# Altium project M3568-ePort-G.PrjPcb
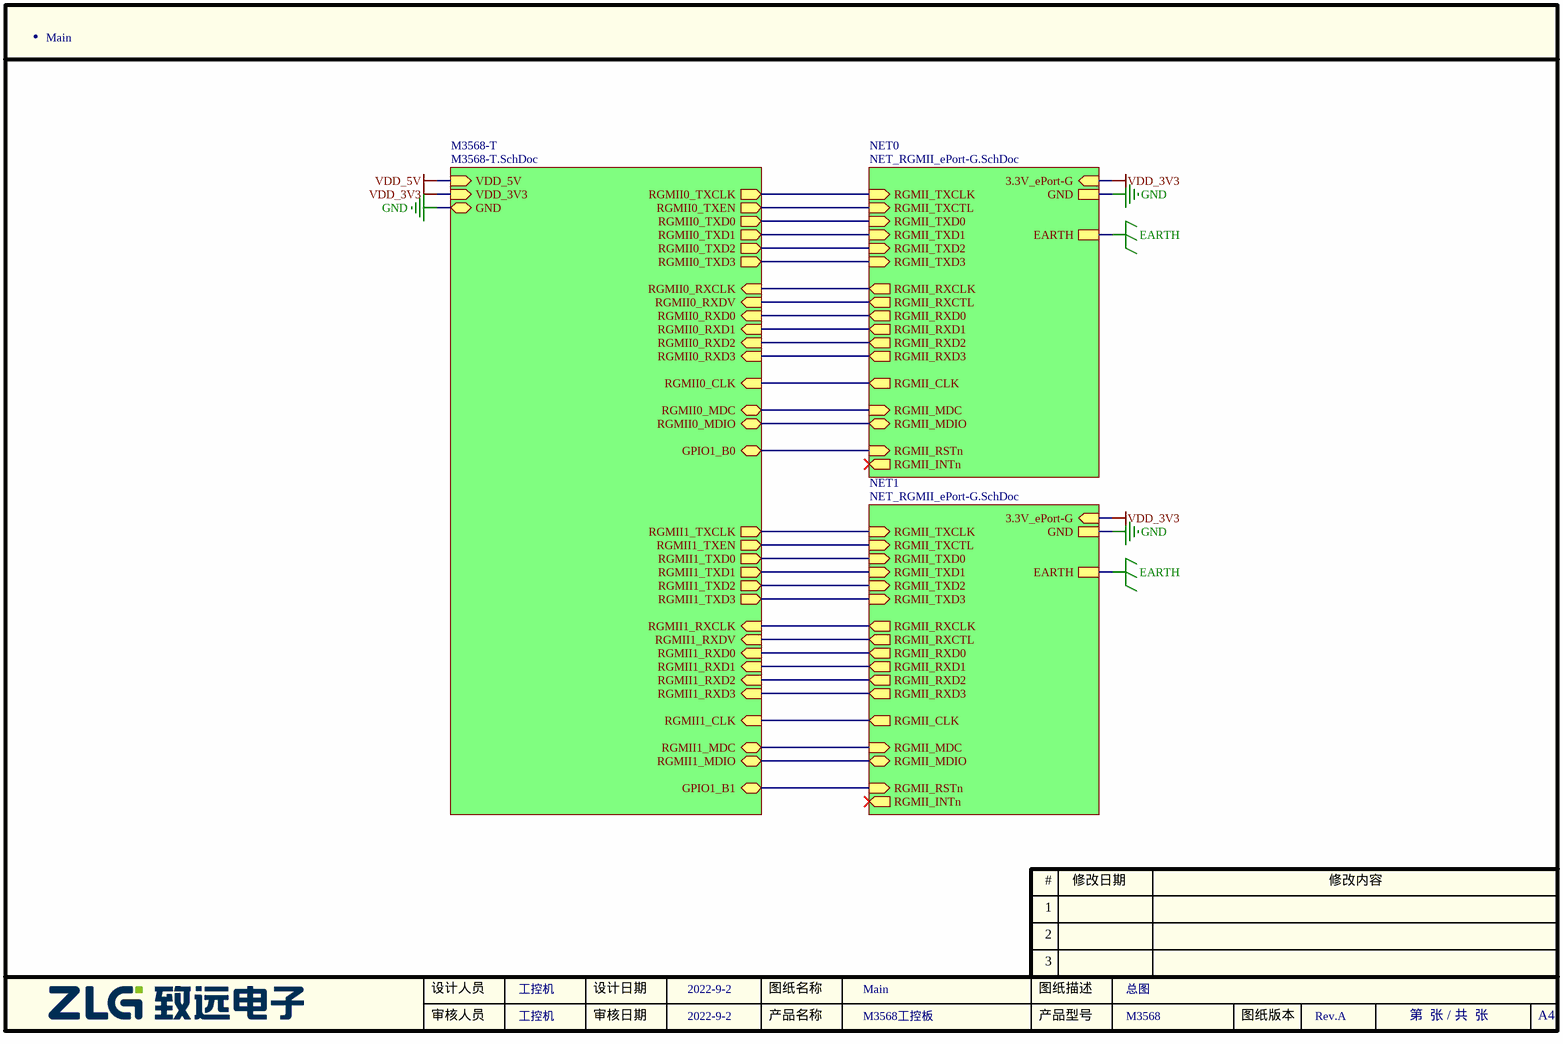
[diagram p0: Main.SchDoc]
3 sheets, 72 parts. Net scope: hierarchical (ports join the sheet entries above them; power ports are global).
Sheets:
  Main.SchDoc
    M3568-T = M3568-T.SchDoc
    NET0 = NET_RGMII_ePort-G.SchDoc
    NET1 = NET_RGMII_ePort-G.SchDoc

## Sheet Main.SchDoc
size A4; PageSetup: Record=PageOptions¦CenterHorizontal=True¦CenterVertical=True¦PrintScale=1.00¦XCorrection=1.00¦YCorrection=1.00¦PrintKind=0¦BorderSize=5000000¦LeftOffset=0¦BottomOffset=0¦Orientation=2¦PaperLength=1000¦PaperWidth=1000¦Scale=100¦PaperSource=7¦PrintQuality=600¦MediaType=1¦DitherType=10¦PaperKind=A4¦PrintScaleMode=1

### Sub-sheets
M3568-T = M3568-T.SchDoc: VDD_5V (in), VDD_3V3 (in), GND (bidir), RGMII1_TXEN (out), RGMII1_TXCLK (out), RGMII1_TXD3 (out), RGMII1_TXD2 (out), RGMII1_TXD1 (out), RGMII1_TXD0 (out), RGMII1_MDC (bidir), RGMII1_MDIO (bidir), RGMII1_CLK (in), RGMII1_RXD2 (in), RGMII1_RXD3 (in), RGMII1_RXD0 (in), RGMII1_RXD1 (in), RGMII1_RXCLK (in), RGMII1_RXDV (in), RGMII0_TXD3 (out), RGMII0_TXD2 (out), RGMII0_TXD1 (out), RGMII0_TXD0 (out), RGMII0_TXEN (out), RGMII0_TXCLK (out), RGMII0_MDIO (bidir), RGMII0_RXD3 (in), RGMII0_RXD2 (in), RGMII0_RXD1 (in), RGMII0_RXD0 (in), RGMII0_RXDV (in), RGMII0_RXCLK (in), RGMII0_MDC (bidir), RGMII0_CLK (in), GPIO1_B1 (bidir), GPIO1_B0 (bidir)
NET0 = NET_RGMII_ePort-G.SchDoc: GND, RGMII_INTn (out), RGMII_RXD0 (out), RGMII_RXD2 (out), RGMII_RXCTL (out), RGMII_RXD1 (out), RGMII_TXCLK (in), RGMII_RXD3 (out), RGMII_TXD2 (in), RGMII_MDIO (bidir), RGMII_TXD3 (in), RGMII_TXCTL (in), RGMII_TXD1 (in), RGMII_RXCLK (out), RGMII_MDC (in), RGMII_TXD0 (in), RGMII_RSTn (in), EARTH, RGMII_CLK (out), 3.3V_ePort-G (in)
NET1 = NET_RGMII_ePort-G.SchDoc: GND, RGMII_INTn (out), RGMII_RXD0 (out), RGMII_RXD2 (out), RGMII_RXCTL (out), RGMII_RXD1 (out), RGMII_TXCLK (in), RGMII_RXD3 (out), RGMII_TXD2 (in), RGMII_MDIO (bidir), RGMII_TXD3 (in), RGMII_TXCTL (in), RGMII_TXD1 (in), RGMII_RXCLK (out), RGMII_MDC (in), RGMII_TXD0 (in), RGMII_RSTn (in), EARTH, RGMII_CLK (out), 3.3V_ePort-G (in)

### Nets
EARTH: sheet NET0/EARTH, sheet NET1/EARTH
GND: sheet M3568-T/GND, sheet NET0/GND, sheet NET1/GND
VDD_3V3: sheet M3568-T/VDD_3V3, sheet NET0/3.3V_ePort-G, sheet NET1/3.3V_ePort-G  [project net 3.3V_ePort-G]
RGMII_CLK: sheet M3568-T/RGMII1_CLK, sheet NET1/RGMII_CLK
RGMII_CLK: sheet M3568-T/RGMII0_CLK, sheet NET0/RGMII_CLK  [a separate net that carries the same name]
RGMII_MDC: sheet M3568-T/RGMII1_MDC, sheet NET1/RGMII_MDC
RGMII_MDC: sheet M3568-T/RGMII0_MDC, sheet NET0/RGMII_MDC  [a separate net that carries the same name]
RGMII_MDIO: sheet M3568-T/RGMII1_MDIO, sheet NET1/RGMII_MDIO
RGMII_MDIO: sheet M3568-T/RGMII0_MDIO, sheet NET0/RGMII_MDIO  [a separate net that carries the same name]
RGMII_RSTn: sheet M3568-T/GPIO1_B1, sheet NET1/RGMII_RSTn
RGMII_RSTn: sheet M3568-T/GPIO1_B0, sheet NET0/RGMII_RSTn  [a separate net that carries the same name]
RGMII_RXCLK: sheet M3568-T/RGMII1_RXCLK, sheet NET1/RGMII_RXCLK
RGMII_RXCLK: sheet M3568-T/RGMII0_RXCLK, sheet NET0/RGMII_RXCLK  [a separate net that carries the same name]
RGMII_RXCTL: sheet M3568-T/RGMII1_RXDV, sheet NET1/RGMII_RXCTL
RGMII_RXCTL: sheet M3568-T/RGMII0_RXDV, sheet NET0/RGMII_RXCTL  [a separate net that carries the same name]
RGMII_RXD0: sheet M3568-T/RGMII1_RXD0, sheet NET1/RGMII_RXD0
RGMII_RXD0: sheet M3568-T/RGMII0_RXD0, sheet NET0/RGMII_RXD0  [a separate net that carries the same name]
RGMII_RXD1: sheet M3568-T/RGMII1_RXD1, sheet NET1/RGMII_RXD1
RGMII_RXD1: sheet M3568-T/RGMII0_RXD1, sheet NET0/RGMII_RXD1  [a separate net that carries the same name]
RGMII_RXD2: sheet M3568-T/RGMII1_RXD2, sheet NET1/RGMII_RXD2
RGMII_RXD2: sheet M3568-T/RGMII0_RXD2, sheet NET0/RGMII_RXD2  [a separate net that carries the same name]
RGMII_RXD3: sheet M3568-T/RGMII1_RXD3, sheet NET1/RGMII_RXD3
RGMII_RXD3: sheet M3568-T/RGMII0_RXD3, sheet NET0/RGMII_RXD3  [a separate net that carries the same name]
RGMII_TXCLK: sheet M3568-T/RGMII1_TXCLK, sheet NET1/RGMII_TXCLK
RGMII_TXCLK: sheet M3568-T/RGMII0_TXCLK, sheet NET0/RGMII_TXCLK  [a separate net that carries the same name]
RGMII_TXCTL: sheet M3568-T/RGMII1_TXEN, sheet NET1/RGMII_TXCTL
RGMII_TXCTL: sheet M3568-T/RGMII0_TXEN, sheet NET0/RGMII_TXCTL  [a separate net that carries the same name]
RGMII_TXD0: sheet M3568-T/RGMII1_TXD0, sheet NET1/RGMII_TXD0
RGMII_TXD0: sheet M3568-T/RGMII0_TXD0, sheet NET0/RGMII_TXD0  [a separate net that carries the same name]
RGMII_TXD1: sheet M3568-T/RGMII1_TXD1, sheet NET1/RGMII_TXD1
RGMII_TXD1: sheet M3568-T/RGMII0_TXD1, sheet NET0/RGMII_TXD1  [a separate net that carries the same name]
RGMII_TXD2: sheet M3568-T/RGMII1_TXD2, sheet NET1/RGMII_TXD2
RGMII_TXD2: sheet M3568-T/RGMII0_TXD2, sheet NET0/RGMII_TXD2  [a separate net that carries the same name]
RGMII_TXD3: sheet M3568-T/RGMII1_TXD3, sheet NET1/RGMII_TXD3
RGMII_TXD3: sheet M3568-T/RGMII0_TXD3, sheet NET0/RGMII_TXD3  [a separate net that carries the same name]

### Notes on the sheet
- Main
- 工控机
- 2022-9-2
- M3568工控板
- 总图
- M3568
- Rev.A

## Sheet M3568-T.SchDoc
size A3; PageSetup: Record=PageOptions¦CenterHorizontal=True¦CenterVertical=True¦PrintScale=1.00¦XCorrection=1.00¦YCorrection=1.00¦PrintKind=0¦BorderSize=5000000¦LeftOffset=0¦BottomOffset=0¦Orientation=2¦PaperLength=1000¦PaperWidth=1000¦Scale=100¦PaperSource=7¦PrintQuality=600¦MediaType=1¦DitherType=10¦PaperKind=A4¦PrintScaleMode=1
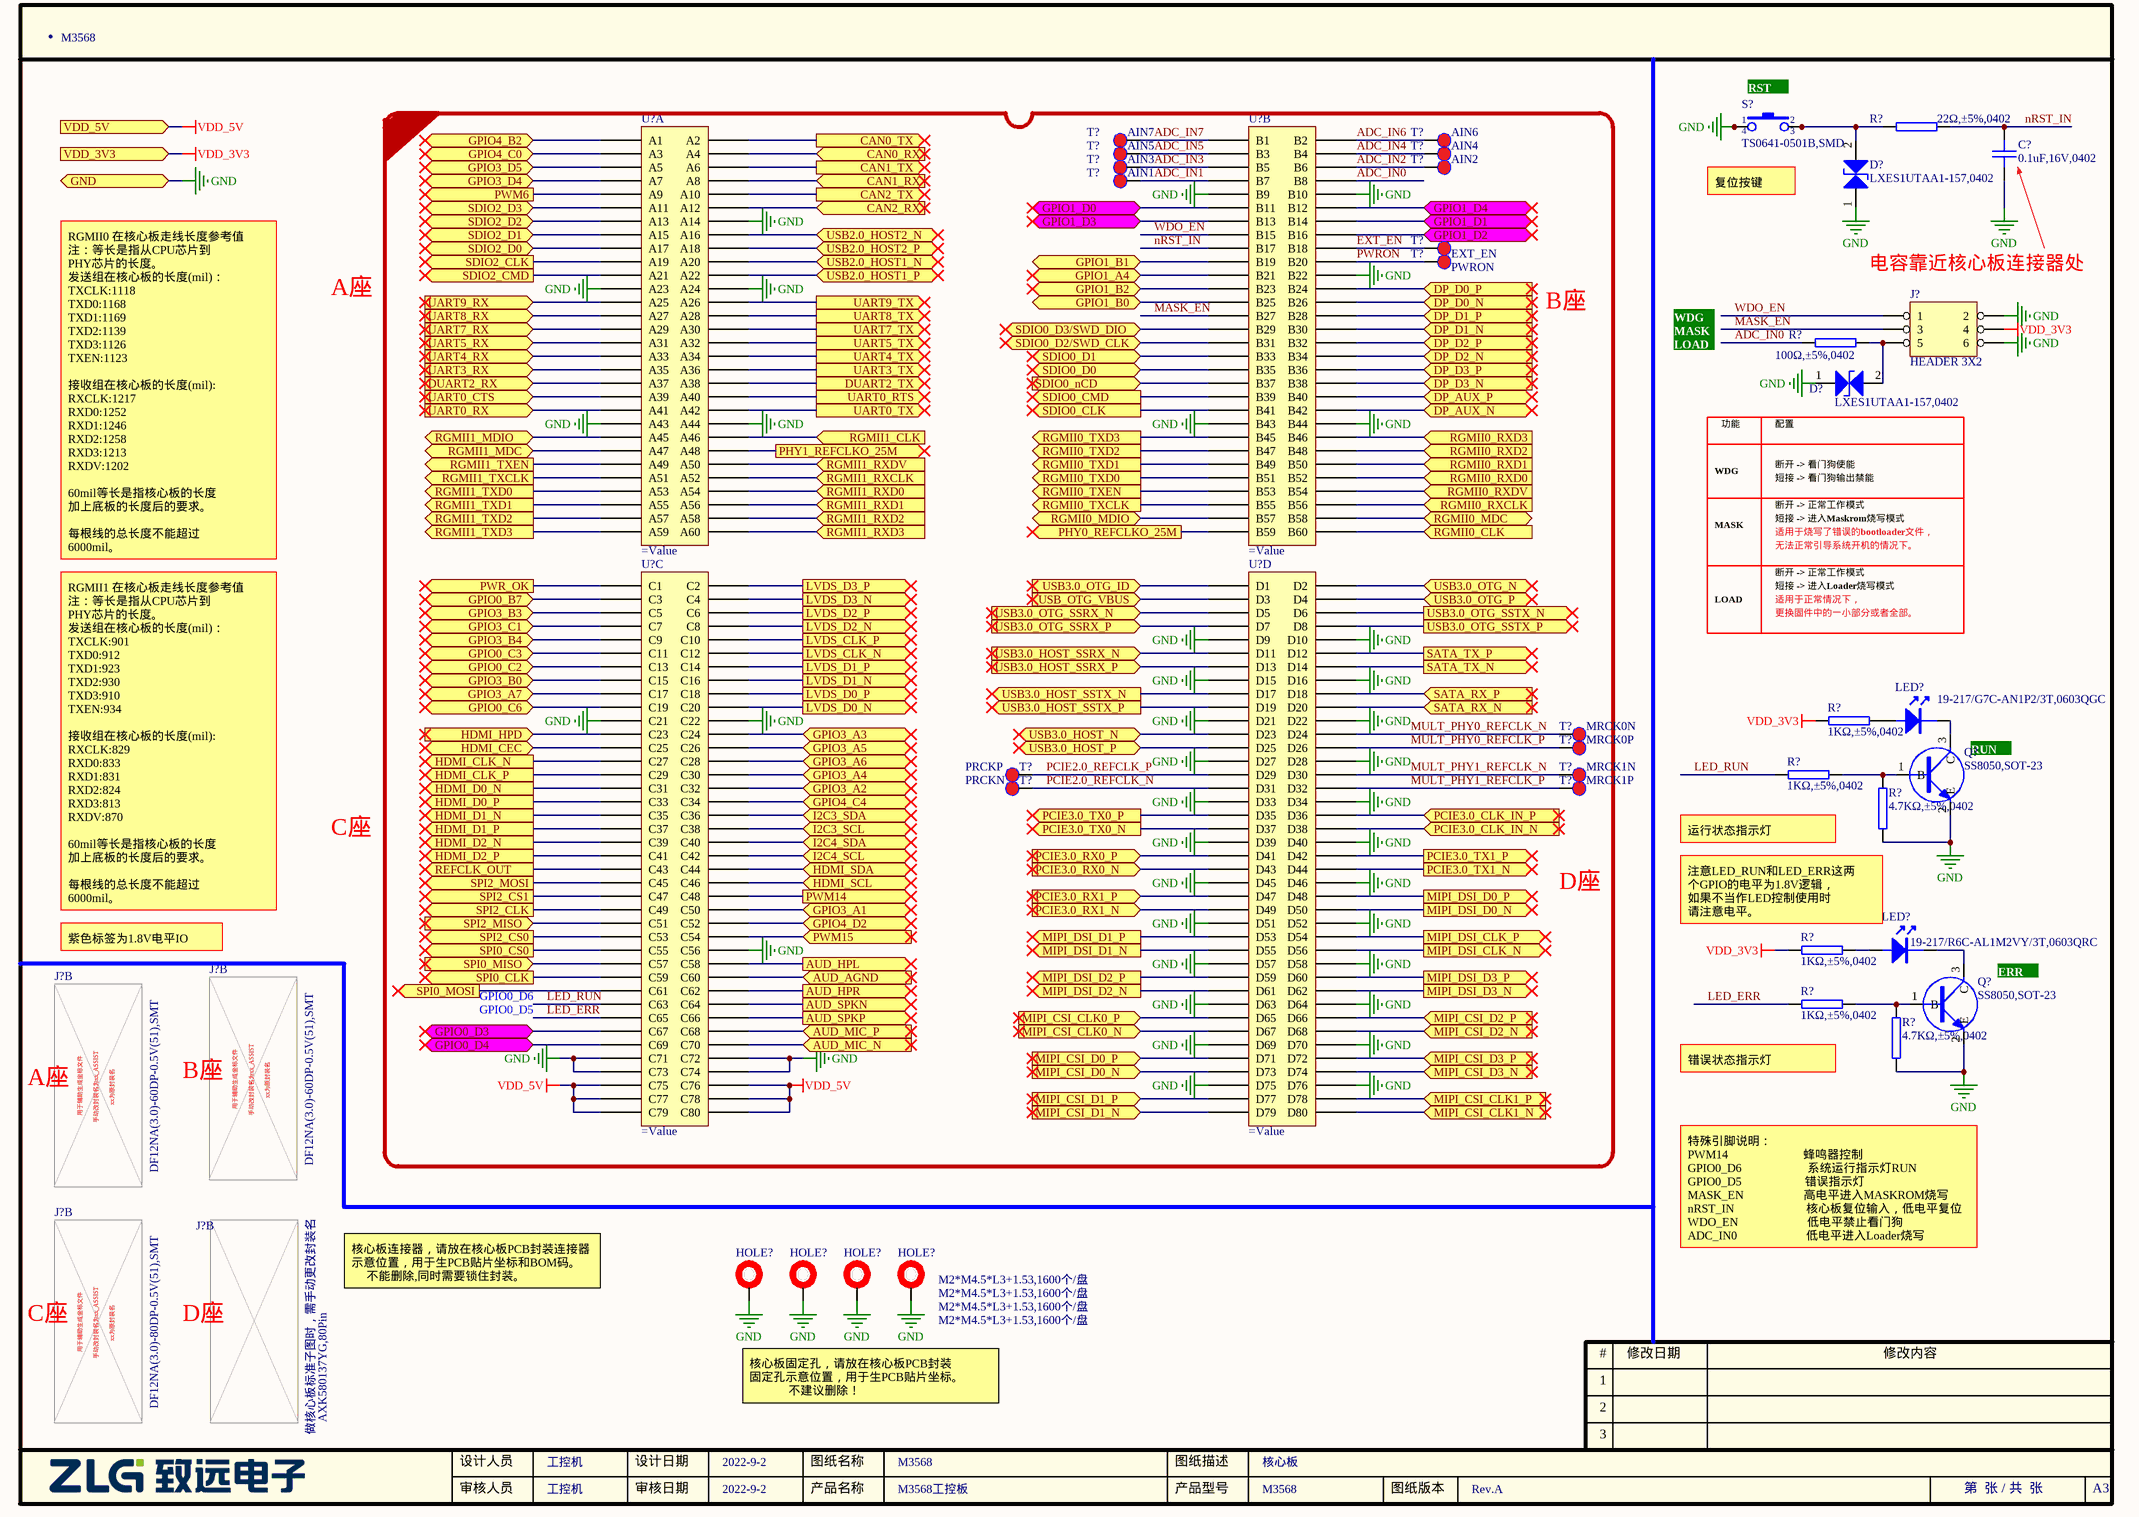
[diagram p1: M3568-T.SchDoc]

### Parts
(Parts that share a designator on the sheet are numbered #1, #2 ... from top to bottom, then left to right.)
C?  0.1uF,16V,0402  [0402C]
D?#1  LXES1UTAA1-157,0402  [0402D]
D?#2  LXES1UTAA1-157,0402  [0402D]
HOLE?#1  M2*M4.5*L3+1.53,1600个/盘  [Mou-Hole-300D450W310H-SMD]
HOLE?#2  M2*M4.5*L3+1.53,1600个/盘  [Mou-Hole-300D450W310H-SMD]
HOLE?#3  M2*M4.5*L3+1.53,1600个/盘  [Mou-Hole-300D450W310H-SMD]
HOLE?#4  M2*M4.5*L3+1.53,1600个/盘  [Mou-Hole-300D450W310H-SMD]
J?#1  HEADER 3X2  [IDC-6-2.54]
J?#2  DF12NA(3.0)-60DP-0.5V(51),SMT  [SMTCON_DF12NA(3.0)-60DP-0.5V(51)_ASSIST]  (part B of 2)
J?#3  DF12NA(3.0)-60DP-0.5V(51),SMT  [SMTCON_DF12NA(3.0)-60DP-0.5V(51)_ASSIST]  (part B of 2)
J?#4  DF12NA(3.0)-80DP-0.5V(51),SMT  [SMTCON_DF12NA(3.0)-80DP-0.5V(51)_ASSIST]  (part B of 2)
J?#5  AXK580137YG,80Pin  [SMT50L2320W500H350-80FEMALE(false)]  (part B of 2)
LED?#1  19-217/G7C-AN1P2/3T,0603QGC  [LED-0603]
LED?#2  19-217/R6C-AL1M2VY/3T,0603QRC  [LED-0603]
Q?#1  SS8050,SOT-23  [SOT-23]
Q?#2  SS8050,SOT-23  [SOT-23]
R?#1  22Ω,±5%,0402  [0402R]
R?#2  100Ω,±5%,0402  [0402R]
R?#3  1KΩ,±5%,0402  [0402R]
R?#4  1KΩ,±5%,0402  [0402R]
R?#5  4.7KΩ,±5%,0402  [0402R]
R?#6  1KΩ,±5%,0402  [0402R]
R?#7  1KΩ,±5%,0402  [0402R]
R?#8  4.7KΩ,±5%,0402  [0402R]
S?  TS0641-0501B,SMD  [KEY-6S]
T?#1  AIN7  [PAD-40]  (no BOM)
T?#2  AIN6  [PAD-40]  (no BOM)
T?#3  AIN5  [PAD-40]  (no BOM)
T?#4  AIN4  [PAD-40]  (no BOM)
T?#5  AIN3  [PAD-40]  (no BOM)
T?#6  AIN2  [PAD-40]  (no BOM)
T?#7  AIN1  [PAD-40]  (no BOM)
T?#8  EXT_EN  [PAD-40]  (no BOM)
T?#9  PWRON  [PAD-40]  (no BOM)
T?#10  MRCK0N  [PAD-40]  (no BOM)
T?#11  MRCK0P  [PAD-40]  (no BOM)
T?#12  PRCKP  [PAD-40]  (no BOM)
T?#13  MRCK1N  [PAD-40]  (no BOM)
T?#14  PRCKN  [PAD-40]  (no BOM)
T?#15  MRCK1P  [PAD-40]  (no BOM)
U?#1  (no value)  [M3568-T_REVA]  (part A of 4)
U?#2  (no value)  [M3568-T_REVA]  (part B of 4)
U?#3  (no value)  [M3568-T_REVA]  (part C of 4)
U?#4  (no value)  [M3568-T_REVA]  (part D of 4)

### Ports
AUD_AGND (in), AUD_HPL (out), AUD_HPR (out), AUD_MIC_N (in), AUD_MIC_P (in), AUD_SPKN (out), AUD_SPKP (out), CAN0_RX (in), CAN0_TX (out), CAN1_RX (in), CAN1_TX (out), CAN2_RX (in), CAN2_TX (out), DP_AUX_N (bidir), DP_AUX_P (bidir), DP_D0_N (in), DP_D0_P (in), DP_D1_N (in), DP_D1_P (in), DP_D2_N (in), DP_D2_P (in), DP_D3_N (in), DP_D3_P (in), DUART2_RX (in), DUART2_TX (out), GND (bidir), GPIO0_B7 (bidir), GPIO0_C2 (bidir), GPIO0_C3 (bidir), GPIO0_C6 (bidir), GPIO0_D3 (bidir), GPIO0_D4 (bidir), GPIO1_A4 (bidir), GPIO1_B0 (bidir), GPIO1_B1 (bidir), GPIO1_B2 (bidir), GPIO1_D0 (bidir), GPIO1_D1 (bidir), GPIO1_D2 (bidir), GPIO1_D3 (bidir), GPIO1_D4 (bidir), GPIO3_A1 (bidir), GPIO3_A2 (bidir), GPIO3_A3 (bidir), GPIO3_A4 (bidir), GPIO3_A5 (bidir), GPIO3_A6 (bidir), GPIO3_A7 (bidir), GPIO3_B0 (bidir), GPIO3_B3 (bidir), GPIO3_B4 (bidir), GPIO3_C1 (bidir), GPIO3_D4 (bidir), GPIO3_D5 (bidir), GPIO4_B2 (bidir), GPIO4_C0 (bidir), GPIO4_C4 (bidir), GPIO4_D2 (bidir), HDMI_CEC (bidir), HDMI_CLK_N (out), HDMI_CLK_P (out), HDMI_D0_N (out), HDMI_D0_P (out), HDMI_D1_N (out), HDMI_D1_P (out), HDMI_D2_N (out), HDMI_D2_P (out), HDMI_HPD (in), HDMI_SCL (bidir), HDMI_SDA (bidir), I2C3_SCL (bidir), I2C3_SDA (bidir), I2C4_SCL (bidir), I2C4_SDA (bidir), LVDS_CLK_N (out), LVDS_CLK_P (out), LVDS_D0_N (out), LVDS_D0_P (out), LVDS_D1_N (out), LVDS_D1_P (out), LVDS_D2_N (out), LVDS_D2_P (out), LVDS_D3_N (out), LVDS_D3_P (out), MIPI_CSI_CLK0_N (in), MIPI_CSI_CLK0_P (in), MIPI_CSI_CLK1_N (in), MIPI_CSI_CLK1_P (in), MIPI_CSI_D0_N (in), MIPI_CSI_D0_P (in), MIPI_CSI_D1_N (in), MIPI_CSI_D1_P (in), MIPI_CSI_D2_N (in), MIPI_CSI_D2_P (in), MIPI_CSI_D3_N (in), MIPI_CSI_D3_P (in), MIPI_DSI_CLK_N (out), MIPI_DSI_CLK_P (out), MIPI_DSI_D0_N (out), MIPI_DSI_D0_P (out), MIPI_DSI_D1_N (out), MIPI_DSI_D1_P (out), MIPI_DSI_D2_N (out), MIPI_DSI_D2_P (out), MIPI_DSI_D3_N (out), MIPI_DSI_D3_P (out), PCIE3.0_CLK_IN_N (in), PCIE3.0_CLK_IN_P (in), PCIE3.0_RX0_N (in), PCIE3.0_RX0_P (in), PCIE3.0_RX1_N (in), PCIE3.0_RX1_P (in), PCIE3.0_TX0_N (out), PCIE3.0_TX0_P (out), PCIE3.0_TX1_N (out), PCIE3.0_TX1_P (out), PHY0_REFCLKO_25M (out), PHY1_REFCLKO_25M (out), PWM6 (out), PWM14 (out), PWM15 (in), PWR_OK (out), REFCLK_OUT (out), RGMII0_CLK (in), RGMII0_MDC (bidir), RGMII0_MDIO (bidir), RGMII0_RXCLK (in), RGMII0_RXD0 (in), RGMII0_RXD1 (in), RGMII0_RXD2 (in), RGMII0_RXD3 (in), RGMII0_RXDV (in), RGMII0_TXCLK (out), RGMII0_TXD0 (out), RGMII0_TXD1 (out), RGMII0_TXD2 (out), RGMII0_TXD3 (out), RGMII0_TXEN (out), RGMII1_CLK (in), RGMII1_MDC (bidir), RGMII1_MDIO (bidir), RGMII1_RXCLK (in), RGMII1_RXD0 (in), RGMII1_RXD1 (in), RGMII1_RXD2 (in), RGMII1_RXD3 (in), RGMII1_RXDV (in), RGMII1_TXCLK (out), RGMII1_TXD0 (out), RGMII1_TXD1 (out), RGMII1_TXD2 (out), RGMII1_TXD3 (out), RGMII1_TXEN (out), SATA_RX_N (in), SATA_RX_P (in), SATA_TX_N (out), SATA_TX_P (out), SDIO0_CLK (out), SDIO0_CMD (out), SDIO0_D0 (bidir), SDIO0_D1 (bidir), SDIO0_D2/SWD_CLK (bidir), SDIO0_D3/SWD_DIO (bidir), SDIO0_nCD (in), SDIO2_CLK (out), SDIO2_CMD (out), SDIO2_D0 (bidir), SDIO2_D1 (bidir), SDIO2_D2 (bidir), SDIO2_D3 (bidir), SPI0_CLK (out), SPI0_CS0 (out), SPI0_MISO (in), SPI0_MOSI (out), SPI2_CLK (out), SPI2_CS0 (out), SPI2_CS1 (out), SPI2_MISO (in), SPI2_MOSI (out), UART0_CTS (in), UART0_RTS (out), UART0_RX (in), UART0_TX (out), UART3_RX (in), UART3_TX (out), UART4_RX (in), UART4_TX (out), UART5_RX (in), UART5_TX (out), UART7_RX (in), UART7_TX (out), UART8_RX (in), UART8_TX (out), UART9_RX (in), UART9_TX (out), USB2.0_HOST1_N (bidir), USB2.0_HOST1_P (bidir), USB2.0_HOST2_N (bidir), USB2.0_HOST2_P (bidir), USB3.0_HOST_N (bidir), USB3.0_HOST_P (bidir), USB3.0_HOST_SSRX_N (in), USB3.0_HOST_SSRX_P (in), USB3.0_HOST_SSTX_N (out), USB3.0_HOST_SSTX_P (out), USB3.0_OTG_ID (in), USB3.0_OTG_N (bidir), USB3.0_OTG_P (bidir), USB3.0_OTG_SSRX_N (in), USB3.0_OTG_SSRX_P (in), USB3.0_OTG_SSTX_N (out), USB3.0_OTG_SSTX_P (out), USB_OTG_VBUS (in), VDD_3V3 (in), VDD_5V (in)

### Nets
GND: C?.1 D?#1.1(A) D?#2.1(A) HOLE?#1.1 HOLE?#2.1 HOLE?#3.1 HOLE?#4.1 J?#1.2 J?#1.6 Q?#1.2(E) Q?#2.2(E) R?#5.1 R?#8.1 S?.1 S?.4 U?#1.A14 U?#1.A23 U?#1.A24 U?#1.A43 U?#1.A44 U?#2.B9 U?#2.B10 U?#2.B22 U?#2.B43 U?#2.B44 U?#3.C21 U?#3.C22 U?#3.C56 U?#3.C71 U?#3.C72 U?#3.C73 U?#3.C74 U?#4.D9 U?#4.D10 U?#4.D15 U?#4.D16 U?#4.D21 U?#4.D22 U?#4.D27 U?#4.D28 U?#4.D33 U?#4.D34 U?#4.D39 U?#4.D40 U?#4.D45 U?#4.D46 U?#4.D51 U?#4.D52 U?#4.D57 U?#4.D58 U?#4.D63 U?#4.D64 U?#4.D69 U?#4.D70 U?#4.D75 U?#4.D76 ; port GND
VDD_3V3: J?#1.4 R?#3.1 R?#6.1 ; port VDD_3V3  [project net 3.3V_ePort-G]
VDD_5V: U?#3.C75 U?#3.C76 U?#3.C77 U?#3.C78 U?#3.C79 U?#3.C80 ; port VDD_5V
ADC_IN0: R?#2.1 U?#2.B8
ADC_IN1: T?#7.1 U?#2.B7
ADC_IN2: T?#6.1 U?#2.B6
ADC_IN3: T?#5.1 U?#2.B5
ADC_IN4: T?#4.1 U?#2.B4
ADC_IN5: T?#3.1 U?#2.B3
ADC_IN6: T?#2.1 U?#2.B2
ADC_IN7: T?#1.1 U?#2.B1
EXT_EN: T?#8.1 U?#2.B18
LED_ERR: R?#7.1 U?#3.C65
LED_RUN: R?#4.1 U?#3.C63
MASK_EN: J?#1.3 U?#2.B27
MULT_PHY0_REFCLK_N: T?#10.1 U?#4.D24
MULT_PHY0_REFCLK_P: T?#11.1 U?#4.D26
MULT_PHY1_REFCLK_N: T?#13.1 U?#4.D30
MULT_PHY1_REFCLK_P: T?#15.1 U?#4.D32
nRST_IN: C?.2 R?#1.2 U?#2.B17
PCIE2.0_REFCLK_N: T?#14.1 U?#4.D31
PCIE2.0_REFCLK_P: T?#12.1 U?#4.D29
PWRON: T?#9.1 U?#2.B20
RGMII_CLK: U?#1.A46 ; port RGMII1_CLK
RGMII_CLK: U?#2.B60 ; port RGMII0_CLK  [a separate net that carries the same name]
RGMII_MDC: U?#1.A47 ; port RGMII1_MDC
RGMII_MDC: U?#2.B58 ; port RGMII0_MDC  [a separate net that carries the same name]
RGMII_MDIO: U?#1.A45 ; port RGMII1_MDIO
RGMII_MDIO: U?#2.B57 ; port RGMII0_MDIO  [a separate net that carries the same name]
RGMII_RSTn: U?#2.B19 ; port GPIO1_B1
RGMII_RSTn: U?#2.B25 ; port GPIO1_B0  [a separate net that carries the same name]
RGMII_RXCLK: U?#1.A52 ; port RGMII1_RXCLK
RGMII_RXCLK: U?#2.B56 ; port RGMII0_RXCLK  [a separate net that carries the same name]
RGMII_RXCTL: U?#1.A50 ; port RGMII1_RXDV
RGMII_RXCTL: U?#2.B54 ; port RGMII0_RXDV  [a separate net that carries the same name]
RGMII_RXD0: U?#1.A54 ; port RGMII1_RXD0
RGMII_RXD0: U?#2.B52 ; port RGMII0_RXD0  [a separate net that carries the same name]
RGMII_RXD1: U?#1.A56 ; port RGMII1_RXD1
RGMII_RXD1: U?#2.B50 ; port RGMII0_RXD1  [a separate net that carries the same name]
RGMII_RXD2: U?#1.A58 ; port RGMII1_RXD2
RGMII_RXD2: U?#2.B48 ; port RGMII0_RXD2  [a separate net that carries the same name]
RGMII_RXD3: U?#1.A60 ; port RGMII1_RXD3
RGMII_RXD3: U?#2.B46 ; port RGMII0_RXD3  [a separate net that carries the same name]
RGMII_TXCLK: U?#1.A51 ; port RGMII1_TXCLK
RGMII_TXCLK: U?#2.B55 ; port RGMII0_TXCLK  [a separate net that carries the same name]
RGMII_TXCTL: U?#1.A49 ; port RGMII1_TXEN
RGMII_TXCTL: U?#2.B53 ; port RGMII0_TXEN  [a separate net that carries the same name]
RGMII_TXD0: U?#1.A53 ; port RGMII1_TXD0
RGMII_TXD0: U?#2.B51 ; port RGMII0_TXD0  [a separate net that carries the same name]
RGMII_TXD1: U?#1.A55 ; port RGMII1_TXD1
RGMII_TXD1: U?#2.B49 ; port RGMII0_TXD1  [a separate net that carries the same name]
RGMII_TXD2: U?#1.A57 ; port RGMII1_TXD2
RGMII_TXD2: U?#2.B47 ; port RGMII0_TXD2  [a separate net that carries the same name]
RGMII_TXD3: U?#1.A59 ; port RGMII1_TXD3
RGMII_TXD3: U?#2.B45 ; port RGMII0_TXD3  [a separate net that carries the same name]
WDO_EN: J?#1.1 U?#2.B15
NetD?#1_2: D?#1.2(K) R?#1.1 S?.2 S?.3
NetD?#2_2: D?#2.2(K) J?#1.5 R?#2.2
NetLED?#1_1: LED?#1.1 R?#3.2
NetLED?#1_2: LED?#1.2 Q?#1.3(C)
NetLED?#2_1: LED?#2.1 R?#6.2
NetLED?#2_2: LED?#2.2 Q?#2.3(C)
NetQ?#1_1: Q?#1.1(B) R?#4.2 R?#5.2
NetQ?#2_1: Q?#2.1(B) R?#7.2 R?#8.2
NetU?#1_A1: U?#1.A1 ; port GPIO4_B2
NetU?#1_A2: U?#1.A2 ; port CAN0_TX
NetU?#1_A3: U?#1.A3 ; port GPIO4_C0
NetU?#1_A4: U?#1.A4 ; port CAN0_RX
NetU?#1_A5: U?#1.A5 ; port GPIO3_D5
NetU?#1_A6: U?#1.A6 ; port CAN1_TX
NetU?#1_A7: U?#1.A7 ; port GPIO3_D4
NetU?#1_A8: U?#1.A8 ; port CAN1_RX
NetU?#1_A9: U?#1.A9 ; port PWM6
NetU?#1_A10: U?#1.A10 ; port CAN2_TX
NetU?#1_A11: U?#1.A11 ; port SDIO2_D3
NetU?#1_A12: U?#1.A12 ; port CAN2_RX
NetU?#1_A13: U?#1.A13 ; port SDIO2_D2
NetU?#1_A15: U?#1.A15 ; port SDIO2_D1
NetU?#1_A16: U?#1.A16 ; port USB2.0_HOST2_N
NetU?#1_A17: U?#1.A17 ; port SDIO2_D0
NetU?#1_A18: U?#1.A18 ; port USB2.0_HOST2_P
NetU?#1_A19: U?#1.A19 ; port SDIO2_CLK
NetU?#1_A20: U?#1.A20 ; port USB2.0_HOST1_N
NetU?#1_A21: U?#1.A21 ; port SDIO2_CMD
NetU?#1_A22: U?#1.A22 ; port USB2.0_HOST1_P
NetU?#1_A25: U?#1.A25 ; port UART9_RX
NetU?#1_A26: U?#1.A26 ; port UART9_TX
NetU?#1_A27: U?#1.A27 ; port UART8_RX
NetU?#1_A28: U?#1.A28 ; port UART8_TX
NetU?#1_A29: U?#1.A29 ; port UART7_RX
NetU?#1_A30: U?#1.A30 ; port UART7_TX
NetU?#1_A31: U?#1.A31 ; port UART5_RX
NetU?#1_A32: U?#1.A32 ; port UART5_TX
NetU?#1_A33: U?#1.A33 ; port UART4_RX
NetU?#1_A34: U?#1.A34 ; port UART4_TX
NetU?#1_A35: U?#1.A35 ; port UART3_RX
NetU?#1_A36: U?#1.A36 ; port UART3_TX
NetU?#1_A37: U?#1.A37 ; port DUART2_RX
NetU?#1_A38: U?#1.A38 ; port DUART2_TX
NetU?#1_A39: U?#1.A39 ; port UART0_CTS
NetU?#1_A40: U?#1.A40 ; port UART0_RTS
NetU?#1_A41: U?#1.A41 ; port UART0_RX
NetU?#1_A42: U?#1.A42 ; port UART0_TX
NetU?#1_A48: U?#1.A48 ; port PHY1_REFCLKO_25M
NetU?#2_B11: U?#2.B11 ; port GPIO1_D0
NetU?#2_B12: U?#2.B12 ; port GPIO1_D4
NetU?#2_B13: U?#2.B13 ; port GPIO1_D3
NetU?#2_B14: U?#2.B14 ; port GPIO1_D1
NetU?#2_B16: U?#2.B16 ; port GPIO1_D2
NetU?#2_B21: U?#2.B21 ; port GPIO1_A4
NetU?#2_B23: U?#2.B23 ; port GPIO1_B2
NetU?#2_B24: U?#2.B24 ; port DP_D0_P
NetU?#2_B26: U?#2.B26 ; port DP_D0_N
NetU?#2_B28: U?#2.B28 ; port DP_D1_P
NetU?#2_B29: U?#2.B29 ; port SDIO0_D3/SWD_DIO
NetU?#2_B30: U?#2.B30 ; port DP_D1_N
NetU?#2_B31: U?#2.B31 ; port SDIO0_D2/SWD_CLK
NetU?#2_B32: U?#2.B32 ; port DP_D2_P
NetU?#2_B33: U?#2.B33 ; port SDIO0_D1
NetU?#2_B34: U?#2.B34 ; port DP_D2_N
NetU?#2_B35: U?#2.B35 ; port SDIO0_D0
NetU?#2_B36: U?#2.B36 ; port DP_D3_P
NetU?#2_B37: U?#2.B37 ; port SDIO0_nCD
NetU?#2_B38: U?#2.B38 ; port DP_D3_N
NetU?#2_B39: U?#2.B39 ; port SDIO0_CMD
NetU?#2_B40: U?#2.B40 ; port DP_AUX_P
NetU?#2_B41: U?#2.B41 ; port SDIO0_CLK
NetU?#2_B42: U?#2.B42 ; port DP_AUX_N
NetU?#2_B59: U?#2.B59 ; port PHY0_REFCLKO_25M
NetU?#3_C1: U?#3.C1 ; port PWR_OK
NetU?#3_C2: U?#3.C2 ; port LVDS_D3_P
NetU?#3_C3: U?#3.C3 ; port GPIO0_B7
NetU?#3_C4: U?#3.C4 ; port LVDS_D3_N
NetU?#3_C5: U?#3.C5 ; port GPIO3_B3
NetU?#3_C6: U?#3.C6 ; port LVDS_D2_P
NetU?#3_C7: U?#3.C7 ; port GPIO3_C1
NetU?#3_C8: U?#3.C8 ; port LVDS_D2_N
NetU?#3_C9: U?#3.C9 ; port GPIO3_B4
NetU?#3_C10: U?#3.C10 ; port LVDS_CLK_P
NetU?#3_C11: U?#3.C11 ; port GPIO0_C3
NetU?#3_C12: U?#3.C12 ; port LVDS_CLK_N
NetU?#3_C13: U?#3.C13 ; port GPIO0_C2
NetU?#3_C14: U?#3.C14 ; port LVDS_D1_P
NetU?#3_C15: U?#3.C15 ; port GPIO3_B0
NetU?#3_C16: U?#3.C16 ; port LVDS_D1_N
NetU?#3_C17: U?#3.C17 ; port GPIO3_A7
NetU?#3_C18: U?#3.C18 ; port LVDS_D0_P
NetU?#3_C19: U?#3.C19 ; port GPIO0_C6
NetU?#3_C20: U?#3.C20 ; port LVDS_D0_N
NetU?#3_C23: U?#3.C23 ; port HDMI_HPD
NetU?#3_C24: U?#3.C24 ; port GPIO3_A3
NetU?#3_C25: U?#3.C25 ; port HDMI_CEC
NetU?#3_C26: U?#3.C26 ; port GPIO3_A5
NetU?#3_C27: U?#3.C27 ; port HDMI_CLK_N
NetU?#3_C28: U?#3.C28 ; port GPIO3_A6
NetU?#3_C29: U?#3.C29 ; port HDMI_CLK_P
NetU?#3_C30: U?#3.C30 ; port GPIO3_A4
NetU?#3_C31: U?#3.C31 ; port HDMI_D0_N
NetU?#3_C32: U?#3.C32 ; port GPIO3_A2
NetU?#3_C33: U?#3.C33 ; port HDMI_D0_P
NetU?#3_C34: U?#3.C34 ; port GPIO4_C4
NetU?#3_C35: U?#3.C35 ; port HDMI_D1_N
NetU?#3_C36: U?#3.C36 ; port I2C3_SDA
NetU?#3_C37: U?#3.C37 ; port HDMI_D1_P
NetU?#3_C38: U?#3.C38 ; port I2C3_SCL
NetU?#3_C39: U?#3.C39 ; port HDMI_D2_N
NetU?#3_C40: U?#3.C40 ; port I2C4_SDA
NetU?#3_C41: U?#3.C41 ; port HDMI_D2_P
NetU?#3_C42: U?#3.C42 ; port I2C4_SCL
NetU?#3_C43: U?#3.C43 ; port REFCLK_OUT
NetU?#3_C44: U?#3.C44 ; port HDMI_SDA
NetU?#3_C45: U?#3.C45 ; port SPI2_MOSI
NetU?#3_C46: U?#3.C46 ; port HDMI_SCL
NetU?#3_C47: U?#3.C47 ; port SPI2_CS1
NetU?#3_C48: U?#3.C48 ; port PWM14
NetU?#3_C49: U?#3.C49 ; port SPI2_CLK
NetU?#3_C50: U?#3.C50 ; port GPIO3_A1
NetU?#3_C51: U?#3.C51 ; port SPI2_MISO
NetU?#3_C52: U?#3.C52 ; port GPIO4_D2
NetU?#3_C53: U?#3.C53 ; port SPI2_CS0
NetU?#3_C54: U?#3.C54 ; port PWM15
NetU?#3_C55: U?#3.C55 ; port SPI0_CS0
NetU?#3_C57: U?#3.C57 ; port SPI0_MISO
NetU?#3_C58: U?#3.C58 ; port AUD_HPL
NetU?#3_C59: U?#3.C59 ; port SPI0_CLK
NetU?#3_C60: U?#3.C60 ; port AUD_AGND
NetU?#3_C61: U?#3.C61 ; port SPI0_MOSI
NetU?#3_C62: U?#3.C62 ; port AUD_HPR
NetU?#3_C64: U?#3.C64 ; port AUD_SPKN
NetU?#3_C66: U?#3.C66 ; port AUD_SPKP
NetU?#3_C67: U?#3.C67 ; port GPIO0_D3
NetU?#3_C68: U?#3.C68 ; port AUD_MIC_P
NetU?#3_C69: U?#3.C69 ; port GPIO0_D4
NetU?#3_C70: U?#3.C70 ; port AUD_MIC_N
NetU?#4_D1: U?#4.D1 ; port USB3.0_OTG_ID
NetU?#4_D2: U?#4.D2 ; port USB3.0_OTG_N
NetU?#4_D3: U?#4.D3 ; port USB_OTG_VBUS
NetU?#4_D4: U?#4.D4 ; port USB3.0_OTG_P
NetU?#4_D5: U?#4.D5 ; port USB3.0_OTG_SSRX_N
NetU?#4_D6: U?#4.D6 ; port USB3.0_OTG_SSTX_N
NetU?#4_D7: U?#4.D7 ; port USB3.0_OTG_SSRX_P
NetU?#4_D8: U?#4.D8 ; port USB3.0_OTG_SSTX_P
NetU?#4_D11: U?#4.D11 ; port USB3.0_HOST_SSRX_N
NetU?#4_D12: U?#4.D12 ; port SATA_TX_P
NetU?#4_D13: U?#4.D13 ; port USB3.0_HOST_SSRX_P
NetU?#4_D14: U?#4.D14 ; port SATA_TX_N
NetU?#4_D17: U?#4.D17 ; port USB3.0_HOST_SSTX_N
NetU?#4_D18: U?#4.D18 ; port SATA_RX_P
NetU?#4_D19: U?#4.D19 ; port USB3.0_HOST_SSTX_P
NetU?#4_D20: U?#4.D20 ; port SATA_RX_N
NetU?#4_D23: U?#4.D23 ; port USB3.0_HOST_N
NetU?#4_D25: U?#4.D25 ; port USB3.0_HOST_P
NetU?#4_D35: U?#4.D35 ; port PCIE3.0_TX0_P
NetU?#4_D36: U?#4.D36 ; port PCIE3.0_CLK_IN_P
NetU?#4_D37: U?#4.D37 ; port PCIE3.0_TX0_N
NetU?#4_D38: U?#4.D38 ; port PCIE3.0_CLK_IN_N
NetU?#4_D41: U?#4.D41 ; port PCIE3.0_RX0_P
NetU?#4_D42: U?#4.D42 ; port PCIE3.0_TX1_P
NetU?#4_D43: U?#4.D43 ; port PCIE3.0_RX0_N
NetU?#4_D44: U?#4.D44 ; port PCIE3.0_TX1_N
NetU?#4_D47: U?#4.D47 ; port PCIE3.0_RX1_P
NetU?#4_D48: U?#4.D48 ; port MIPI_DSI_D0_P
NetU?#4_D49: U?#4.D49 ; port PCIE3.0_RX1_N
NetU?#4_D50: U?#4.D50 ; port MIPI_DSI_D0_N
NetU?#4_D53: U?#4.D53 ; port MIPI_DSI_D1_P
NetU?#4_D54: U?#4.D54 ; port MIPI_DSI_CLK_P
NetU?#4_D55: U?#4.D55 ; port MIPI_DSI_D1_N
NetU?#4_D56: U?#4.D56 ; port MIPI_DSI_CLK_N
NetU?#4_D59: U?#4.D59 ; port MIPI_DSI_D2_P
NetU?#4_D60: U?#4.D60 ; port MIPI_DSI_D3_P
NetU?#4_D61: U?#4.D61 ; port MIPI_DSI_D2_N
NetU?#4_D62: U?#4.D62 ; port MIPI_DSI_D3_N
NetU?#4_D65: U?#4.D65 ; port MIPI_CSI_CLK0_P
NetU?#4_D66: U?#4.D66 ; port MIPI_CSI_D2_P
NetU?#4_D67: U?#4.D67 ; port MIPI_CSI_CLK0_N
NetU?#4_D68: U?#4.D68 ; port MIPI_CSI_D2_N
NetU?#4_D71: U?#4.D71 ; port MIPI_CSI_D0_P
NetU?#4_D72: U?#4.D72 ; port MIPI_CSI_D3_P
NetU?#4_D73: U?#4.D73 ; port MIPI_CSI_D0_N
NetU?#4_D74: U?#4.D74 ; port MIPI_CSI_D3_N
NetU?#4_D77: U?#4.D77 ; port MIPI_CSI_D1_P
NetU?#4_D78: U?#4.D78 ; port MIPI_CSI_CLK1_P
NetU?#4_D79: U?#4.D79 ; port MIPI_CSI_D1_N
NetU?#4_D80: U?#4.D80 ; port MIPI_CSI_CLK1_N

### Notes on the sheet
- M3568
- (near S?) RST
- 复位按键
- A座
- B座
- WDG
- (near J?#1) 电容靠近核心板连接器处
- MASK
- LOAD
- 功能
- 配置
- 断开 -> 看门狗使能
- 断开 -> 正常工作模式
- 短接 -> 看门狗输出禁能
- RGMII0 在核心板走线长度参考值
  注：等长是指从CPU芯片到
  PHY芯片的长度。
  发送组在核心板的长度(mil)：
  TXCLK:1118
  TXD0:1168
  TXD1:1169
  TXD2:1139
  TXD3:1126
  TXEN:1123
  接收组在核心板的长度(mil):
  RXCLK:1217
  RXD0:1252
  RXD1:1246
  RXD2:1258
  RXD3:1213
  RXDV:1202
  60mil等长是指核心板的长度
  加上底板的长度后的要求。
  每根线的总长度不能超过
  6000mil。
- 短接 -> 进入Maskrom烧写模式
- 短接 -> 进入Loader烧写模式
- 适用于烧写了错误的bootloader文件，
- 无法正常引导系统开机的情况下。
- 适用于正常情况下，
- 更换固件中的一小部分或者全部。
- (near Q?#1) RUN
- C座
- (near R?#4) 运行状态指示灯
- RGMII1 在核心板走线长度参考值
  注：等长是指从CPU芯片到
  PHY芯片的长度。
  发送组在核心板的长度(mil)：
  TXCLK:901
  TXD0:912
  TXD1:923
  TXD2:930
  TXD3:910
  TXEN:934
  接收组在核心板的长度(mil):
  RXCLK:829
  RXD0:833
  RXD1:831
  RXD2:824
  RXD3:813
  RXDV:870
  60mil等长是指核心板的长度
  加上底板的长度后的要求。
  每根线的总长度不能超过
  6000mil。
- D座
- (near R?#5) 注意LED_RUN和LED_ERR这两
  个GPIO的电平为1.8V逻辑，
  如果不当作LED控制使用时
  请注意电平。
- (near J?#2) 紫色标签为1.8V电平IO
- (near Q?#2) ERR
- GPIO0_D5
- GPIO0_D6
- (near R?#7) 错误状态指示灯
- 特殊引脚说明：
  PWM14                         蜂鸣器控制
  GPIO0_D6                      系统运行指示灯RUN
  GPIO0_D5                     错误指示灯
  MASK_EN                    高电平进入MASKROM烧写
  nRST_IN                        核心板复位输入，低电平复位
  WDO_EN                       低电平禁止看门狗
  ADC_IN0                       低电平进入Loader烧写
- 核心板连接器，请放在核心板PCB封装连接器
  示意位置，用于生PCB贴片坐标和BOM码。
  不能删除,同时需要锁住封装。
- 核心板固定孔，请放在核心板PCB封装
  固定孔示意位置，用于生PCB贴片坐标。
  不建议删除！
- 工控机
- 2022-9-2
- M3568工控板
- 核心板
- Rev.A

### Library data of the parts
C? = 02.01.00263: GRM155R71C104KA88D,0402,MURATA,0.1uF,X7R,±10%,16V,; 旧物料代码: 1.02.17.0006; 名称: 电容; 封装: 0402; 贴片和直插: SMT; 器件优选方案: 通用物料
D?#1 D?#2 = 09.04.00336: LXES1UTAA1-157,0402,MURATA; 名称: ESD静电保护器件; 封装: 0402; 贴片和直插: SMT; PCB备注: 200212CZY; 器件优选方案: 通用物料; 环保状态: RoHS2.0; 生产单位: PCS
HOLE?#1-HOLE?#4 = 27.41.00039: M2*M4.5*L3+1.53,1600个/盘,雄和远景; 旧物料代码: 1.15.03.0047; 名称: 螺柱; 封装: SMT; PCB备注: 160330lmd; 器件优选方案: 通用物料
J?#2 J?#3 = 18.04.00099: DF12NA(3.0)-60DP-0.5V(51),SMT,HRS; 名称: 板对板连接器; 环保状态: RoHS2.0; PCB备注: 210805ZW; 器件优选方案: 待导入物料; 生产单位: PCS
J?#4 = 18.04.00097: DF12NA(3.0)-80DP-0.5V(51),SMT,HRS; 名称: 板对板连接器; 环保状态: RoHS2.0; PCB备注: 210805ZW; 器件优选方案: 待导入物料; 生产单位: PCS
J?#5 = 18.04.00075: AXK580137YG,80Pin,母座,SMT,Pansonic; 名称: 连接器; 厂商: PANASONIC; PCB备注: 190516ZW; 器件优选方案: 通用物料
LED?#1 = 04.04.00003: 19-217/G7C-AN1P2/3T,0603QGC,SMD,BRIGHT,绿色,; 旧物料代码: 1.04.05.0009; 名称: 发光二极管; 封装: 0603; 贴片和直插: SMT; 器件优选方案: 通用物料
LED?#2 = 04.04.00004: 19-217/R6C-AL1M2VY/3T,0603QRC,SMD,BRIGHT,红色,; 旧物料代码: 1.04.05.0008; 名称: 发光二极管; 封装: 0603; 贴片和直插: SMT; 器件优选方案: 通用物料
Q?#1 Q?#2 = 05.01.00095: SS8050,SOT-23,JCET,NPN,; 旧物料代码: 1.04.09.0001; 名称: 双极结型晶体管(BJT); 贴片和直插: SMT; 器件优选方案: 通用物料
R?#1 = 01.01.00014: RTT02220JTH,0402,RALEC,22Ω,±5%,1/16W,; 旧物料代码: 1.01.17.0023; 名称: 电阻; 封装: 0402; 贴片和直插: SMT; 器件优选方案: 通用物料
R?#2 = 01.01.00096: RTT02101JTH,0402,RALEC,100Ω,±5%,1/16W; 旧物料代码: 1.01.17.0012; 名称: 电阻; 封装: 0402; 贴片和直插: SMT; 器件优选方案: 通用物料
R?#3 R?#4 R?#6 R?#7 = 01.01.00007: RTT02102JTH,0402,RALEC,1KΩ,±5%,1/16W,; 旧物料代码: 1.01.17.0022; 名称: 电阻; 封装: 0402; 贴片和直插: SMT; 器件优选方案: 通用物料
R?#5 R?#8 = 01.01.00003: RTT02472JTH,0402,RALEC,4.7KΩ,±5%,1/16W,; 旧物料代码: 1.01.17.0019; 名称: 电阻; 封装: 0402; 贴片和直插: SMT; 器件优选方案: 通用物料
S? = 17.01.00005: TS0641-0501B,SMD,DAILYLON,黑色,卷带装,6*6*5.0mm,; 旧物料代码: 1.09.01.0003; 名称: 轻触开关; 封装: SMT; 器件优选方案: 通用物料
T?#1-T?#15 = TEST-DOT
U?#1-U?#4 = M3568-T

## Sheet NET_RGMII_ePort-G.SchDoc
size A4; PageSetup: Record=PageOptions¦CenterHorizontal=True¦CenterVertical=True¦PrintScale=1.00¦XCorrection=1.00¦YCorrection=1.00¦PrintKind=0¦BorderSize=5000000¦LeftOffset=0¦BottomOffset=0¦Orientation=2¦PaperLength=1000¦PaperWidth=1000¦Scale=100¦PaperSource=7¦PrintQuality=600¦MediaType=1¦DitherType=10¦PaperKind=A4¦PrintScaleMode=1
Used 2 times, as channels NET0, NET1. Parts and nets are listed once, with the designators drawn on the sheet.
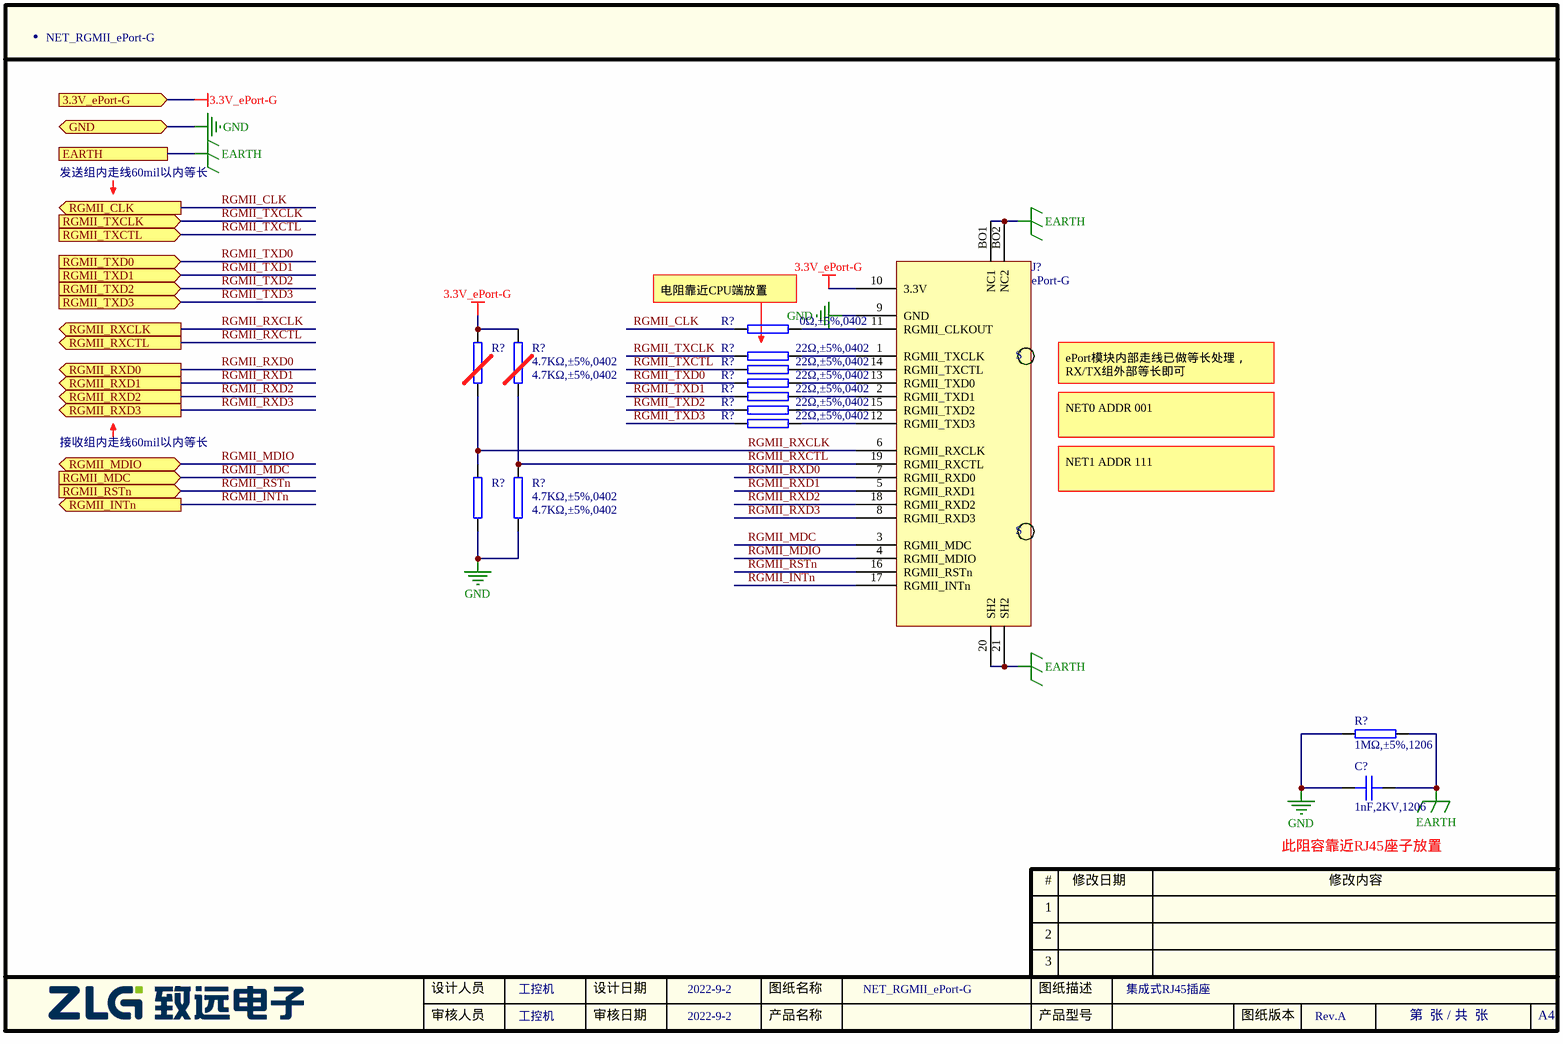
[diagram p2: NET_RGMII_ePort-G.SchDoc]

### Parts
(Parts that share a designator on the sheet are numbered #1, #2 ... from top to bottom, then left to right.)
C?  1nF,2KV,1206  [1206C]
J?  ePort-G
R?#1  0Ω,±5%,0402  [0402RL]
R?#2  22Ω,±5%,0402  [0402RL]
R?#3  22Ω,±5%,0402  [0402RL]
R?#4  22Ω,±5%,0402  [0402RL]
R?#5  4.7KΩ,±5%,0402  [0402RL]
R?#6  4.7KΩ,±5%,0402  [0402RL]
R?#7  22Ω,±5%,0402  [0402RL]
R?#8  22Ω,±5%,0402  [0402RL]
R?#9  22Ω,±5%,0402  [0402RL]
R?#10  4.7KΩ,±5%,0402  [0402RL]
R?#11  4.7KΩ,±5%,0402  [0402RL]
R?#12  1MΩ,±5%,1206  [1206R]

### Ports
3.3V_ePort-G (in), EARTH, GND, RGMII_CLK (out), RGMII_INTn (out), RGMII_MDC (in), RGMII_MDIO (bidir), RGMII_RSTn (in), RGMII_RXCLK (out), RGMII_RXCTL (out), RGMII_RXD0 (out), RGMII_RXD1 (out), RGMII_RXD2 (out), RGMII_RXD3 (out), RGMII_TXCLK (in), RGMII_TXCTL (in), RGMII_TXD0 (in), RGMII_TXD1 (in), RGMII_TXD2 (in), RGMII_TXD3 (in)

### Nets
3.3V_ePort-G: J?.10(3.3V) R?#5.2 R?#6.2 ; port 3.3V_ePort-G
EARTH: C?.2 J?.20(SH2) J?.21(SH2) J?.BO1(NC1) J?.BO2(NC2) R?#12.2 ; port EARTH
GND: C?.1 J?.9(GND) R?#10.1 R?#11.1 R?#12.1 ; port GND
RGMII_CLK: R?#1.1 ; port RGMII_CLK
RGMII_INTn: J?.17(RGMII_INTn) ; port RGMII_INTn
RGMII_MDC: J?.3(RGMII_MDC) ; port RGMII_MDC
RGMII_MDIO: J?.4(RGMII_MDIO) ; port RGMII_MDIO
RGMII_RSTn: J?.16(RGMII_RSTn) ; port RGMII_RSTn
RGMII_RXCLK: J?.6(RGMII_RXCLK) R?#5.1 R?#10.2 ; port RGMII_RXCLK
RGMII_RXCTL: J?.19(RGMII_RXCTL) R?#6.1 R?#11.2 ; port RGMII_RXCTL
RGMII_RXD0: J?.7(RGMII_RXD0) ; port RGMII_RXD0
RGMII_RXD1: J?.5(RGMII_RXD1) ; port RGMII_RXD1
RGMII_RXD2: J?.18(RGMII_RXD2) ; port RGMII_RXD2
RGMII_RXD3: J?.8(RGMII_RXD3) ; port RGMII_RXD3
RGMII_TXCLK: R?#2.1 ; port RGMII_TXCLK
RGMII_TXCTL: R?#3.1 ; port RGMII_TXCTL
RGMII_TXD0: R?#4.1 ; port RGMII_TXD0
RGMII_TXD1: R?#7.1 ; port RGMII_TXD1
RGMII_TXD2: R?#8.1 ; port RGMII_TXD2
RGMII_TXD3: R?#9.1 ; port RGMII_TXD3
NetJ?_1: J?.1(RGMII_TXCLK) R?#2.2
NetJ?_2: J?.2(RGMII_TXD1) R?#7.2
NetJ?_11: J?.11(RGMII_CLKOUT) R?#1.2
NetJ?_12: J?.12(RGMII_TXD3) R?#9.2
NetJ?_13: J?.13(RGMII_TXD0) R?#4.2
NetJ?_14: J?.14(RGMII_TXCTL) R?#3.2
NetJ?_15: J?.15(RGMII_TXD2) R?#8.2

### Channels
NET0: designators C?=C?A J?=J?A R?=R?A#12 R?=R?A#5 R?=R?A#10 R?=R?A#6 R?=R?A#11 R?=R?A#2 R?=R?A#3 R?=R?A#4 R?=R?A#7 R?=R?A#8 R?=R?A#9 R?=R?A#1; ports 3.3V_ePort-G=3.3V_ePort-G EARTH=EARTH GND=GND RGMII_CLK=RGMII_CLK RGMII_INTn=RGMII_INTn_NET0 RGMII_MDC=RGMII_MDC RGMII_MDIO=RGMII_MDIO RGMII_RSTn=RGMII_RSTn RGMII_RXCLK=RGMII_RXCLK RGMII_RXCTL=RGMII_RXCTL RGMII_RXD0=RGMII_RXD0 RGMII_RXD1=RGMII_RXD1 RGMII_RXD2=RGMII_RXD2 RGMII_RXD3=RGMII_RXD3 RGMII_TXCLK=RGMII_TXCLK RGMII_TXCTL=RGMII_TXCTL RGMII_TXD0=RGMII_TXD0 RGMII_TXD1=RGMII_TXD1 RGMII_TXD2=RGMII_TXD2 RGMII_TXD3=RGMII_TXD3
NET1: designators C?=C?B J?=J?B R?=R?B#12 R?=R?B#5 R?=R?B#10 R?=R?B#6 R?=R?B#11 R?=R?B#2 R?=R?B#3 R?=R?B#4 R?=R?B#7 R?=R?B#8 R?=R?B#9 R?=R?B#1; ports 3.3V_ePort-G=3.3V_ePort-G EARTH=EARTH GND=GND RGMII_CLK=RGMII_CLK RGMII_INTn=RGMII_INTn_NET1 RGMII_MDC=RGMII_MDC RGMII_MDIO=RGMII_MDIO RGMII_RSTn=RGMII_RSTn RGMII_RXCLK=RGMII_RXCLK RGMII_RXCTL=RGMII_RXCTL RGMII_RXD0=RGMII_RXD0 RGMII_RXD1=RGMII_RXD1 RGMII_RXD2=RGMII_RXD2 RGMII_RXD3=RGMII_RXD3 RGMII_TXCLK=RGMII_TXCLK RGMII_TXCTL=RGMII_TXCTL RGMII_TXD0=RGMII_TXD0 RGMII_TXD1=RGMII_TXD1 RGMII_TXD2=RGMII_TXD2 RGMII_TXD3=RGMII_TXD3

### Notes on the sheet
- NET_RGMII_ePort-G
- 发送组内走线60mil以内等长
- (near R?#1) 电阻靠近CPU端放置
- ePort模块内部走线已做等长处理，
  RX/TX组外部等长即可
- 接收组内走线60mil以内等长
- NET0 ADDR 001
- NET1 ADDR 111
- (near C?) 此阻容靠近RJ45座子放置
- 工控机
- 2022-9-2
- 集成式RJ45插座
- Rev.A

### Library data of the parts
C? = 02.01.00212: CC1206KKX7RDBB102,1206,YAGEO,1nF,X7R,±10%,2KV,; 旧物料代码: 1.02.03.0003; 名称: 电容; 封装: 1206; 贴片和直插: SMT; 环保状态: RoHS2.0+REACH; 器件优选方案: 不推荐使用; 生产单位: PCS
J? = ePort-G: 千兆集成式RJ45插座
R?#1 = 01.01.00004: RTT02000JTH,0402,RALEC,0Ω,±5%,1/16W,; 名称: 电阻; 封装: 0402; 贴片和直插: SMT; 器件优选方案: 通用物料; 旧物料代码: 1.01.17.0004; 环保状态: RoHS2.0+REACH; 生产单位: PCS
R?#2-R?#4 R?#7-R?#9 = 01.01.00014: RTT02220JTH,0402,RALEC,22Ω,±5%,1/16W,; 名称: 电阻; 封装: 0402; 贴片和直插: SMT; 器件优选方案: 通用物料; 旧物料代码: 1.01.17.0023; 环保状态: RoHS2.0+REACH; 生产单位: PCS
R?#5 R?#6 R?#10 R?#11 = 01.01.00003: RTT02472JTH,0402,RALEC,4.7KΩ,±5%,1/16W,; 名称: 电阻; 封装: 0402; 贴片和直插: SMT; 旧物料代码: 1.01.17.0019; 环保状态: RoHS2.0+REACH; 器件优选方案: 通用物料; 生产单位: PCS
R?#12 = 01.01.00041: RTT06105JTP,1206,RALEC,1MΩ,±5%,1/4W,; 旧物料代码: 1.01.03.0019; 名称: 电阻; 封装: 1206; 贴片和直插: SMT; 环保状态: RoHS2.0+REACH; 器件优选方案: 通用物料; 生产单位: PCS

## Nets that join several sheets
3.3V_ePort-G: M3568-T (J?#1.4 R?#3.1 R?#6.1), NET0 (J?A.10 R?A#5.2 R?A#6.2), NET1 (J?B.10 R?B#5.2 R?B#6.2)
EARTH: NET0 (6 pins), NET1 (6 pins)
GND: M3568-T (56 pins), NET0 (5 pins), NET1 (5 pins)
RGMII_CLK: M3568-T (U?#1.A46), NET1 (R?B#1.1)
RGMII_CLK: M3568-T (U?#2.B60), NET0 (R?A#1.1)
RGMII_MDC: M3568-T (U?#1.A47), NET1 (J?B.3)
RGMII_MDC: M3568-T (U?#2.B58), NET0 (J?A.3)
RGMII_MDIO: M3568-T (U?#1.A45), NET1 (J?B.4)
RGMII_MDIO: M3568-T (U?#2.B57), NET0 (J?A.4)
RGMII_RSTn: M3568-T (U?#2.B19), NET1 (J?B.16)
RGMII_RSTn: M3568-T (U?#2.B25), NET0 (J?A.16)
RGMII_RXCLK: M3568-T (U?#1.A52), NET1 (J?B.6 R?B#5.1 R?B#10.2)
RGMII_RXCLK: M3568-T (U?#2.B56), NET0 (J?A.6 R?A#5.1 R?A#10.2)
RGMII_RXCTL: M3568-T (U?#1.A50), NET1 (J?B.19 R?B#6.1 R?B#11.2)
RGMII_RXCTL: M3568-T (U?#2.B54), NET0 (J?A.19 R?A#6.1 R?A#11.2)
RGMII_RXD0: M3568-T (U?#1.A54), NET1 (J?B.7)
RGMII_RXD0: M3568-T (U?#2.B52), NET0 (J?A.7)
RGMII_RXD1: M3568-T (U?#1.A56), NET1 (J?B.5)
RGMII_RXD1: M3568-T (U?#2.B50), NET0 (J?A.5)
RGMII_RXD2: M3568-T (U?#1.A58), NET1 (J?B.18)
RGMII_RXD2: M3568-T (U?#2.B48), NET0 (J?A.18)
RGMII_RXD3: M3568-T (U?#1.A60), NET1 (J?B.8)
RGMII_RXD3: M3568-T (U?#2.B46), NET0 (J?A.8)
RGMII_TXCLK: M3568-T (U?#1.A51), NET1 (R?B#2.1)
RGMII_TXCLK: M3568-T (U?#2.B55), NET0 (R?A#2.1)
RGMII_TXCTL: M3568-T (U?#1.A49), NET1 (R?B#3.1)
RGMII_TXCTL: M3568-T (U?#2.B53), NET0 (R?A#3.1)
RGMII_TXD0: M3568-T (U?#1.A53), NET1 (R?B#4.1)
RGMII_TXD0: M3568-T (U?#2.B51), NET0 (R?A#4.1)
RGMII_TXD1: M3568-T (U?#1.A55), NET1 (R?B#7.1)
RGMII_TXD1: M3568-T (U?#2.B49), NET0 (R?A#7.1)
RGMII_TXD2: M3568-T (U?#1.A57), NET1 (R?B#8.1)
RGMII_TXD2: M3568-T (U?#2.B47), NET0 (R?A#8.1)
RGMII_TXD3: M3568-T (U?#1.A59), NET1 (R?B#9.1)
RGMII_TXD3: M3568-T (U?#2.B45), NET0 (R?A#9.1)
